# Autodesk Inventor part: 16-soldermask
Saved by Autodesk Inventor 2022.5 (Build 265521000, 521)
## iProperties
Created: 2025-02
Part Number: 16-soldermask
Material: Generic
Document SubType Name: Modeling
Designer: AdminForWorker
Density: 1 g/cm^3
Appearance: Default
Title: 16-soldermask
Author: AdminForWorker
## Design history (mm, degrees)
feature "Body1"
body "Solid1"
